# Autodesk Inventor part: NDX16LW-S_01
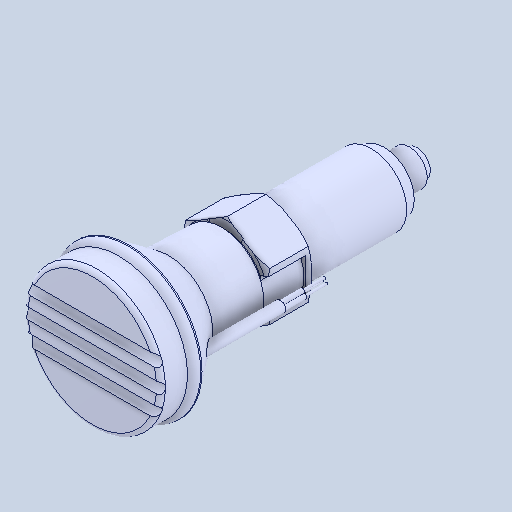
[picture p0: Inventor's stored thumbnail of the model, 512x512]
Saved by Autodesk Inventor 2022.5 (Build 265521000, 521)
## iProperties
Created: 2024-05
Part Number: NDX16LW-S_01
Material: 一般
Document SubType Name: Modeling
Designer: ImaoCorp
Density: 1 g/cm^3
Appearance: 既定
Author: ImaoCorp
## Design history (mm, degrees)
feature "NDX16LW-S_01"
node "ソリッド1"
